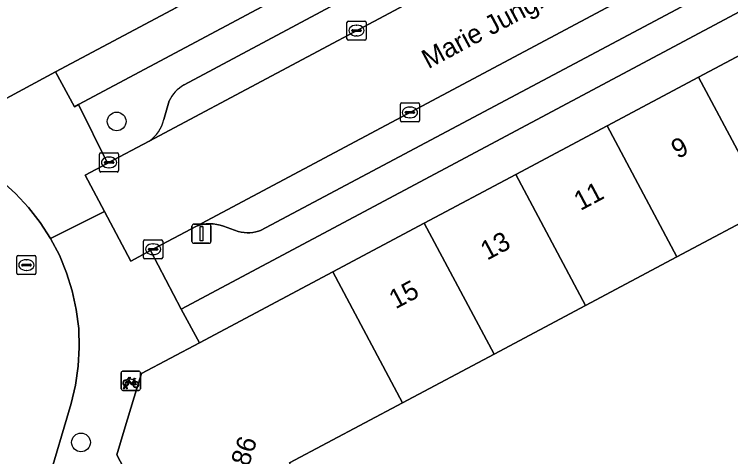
# Model space of a CAD drawing. Extents: x 160304 to 160955, y 383684 to 384161.
# Drawn here: x 160599.67 to 160637.11, y 383862.76 to 383885.89 of the extents above; entities that cross this region are included whole.
import ezdxf

# ---------------------------------------------------------------- set-up
doc = ezdxf.new("R2010")
doc.units = 0
for name, color, linetype in [('IMGEO_Boom', 7, 'Continuous'), ('IMGEO_Erf', 7, 'Continuous'), ('IMGEO_Fietsenrek', 7, 'Continuous'), ('IMGEO_Kolk', 7, 'Continuous'), ('IMGEO_Lichtmast', 7, 'Continuous'), ('IMGEO_Openbare_ruimte_label', 7, 'Continuous'), ('IMGEO_Pand', 7, 'Continuous'), ('IMGEO_Pand_nummerreeks', 7, 'Continuous'), ('IMGEO_Parkeervlak_open', 7, 'Continuous'), ('IMGEO_Rijbaan_lokaal_open', 7, 'Continuous'), ('IMGEO_Voetpad_open', 7, 'Continuous')]:
    doc.layers.add(name, color=color, linetype=linetype)

msp = doc.modelspace()

# ---------------------------------------------------------------- linework, layer by layer
at = {"layer": 'IMGEO_Boom'}
for centre in [(160605.02, 383880.291), (160603.156, 383863.502)]:
    msp.add_circle(centre, 0.489, dxfattribs=at)
at = {"layer": 'IMGEO_Erf'}
for points in [[(160599.049, 383890.783), (160599.714, 383890.581), (160604.477, 383893.118), (160609.434, 383895.758), (160614.39, 383898.398), (160619.346, 383901.038), (160624.41, 383903.736), (160628.072, 383896.861), (160623.008, 383894.164), (160618.052, 383891.524), (160613.096, 383888.884), (160608.139, 383886.243), (160601.831, 383882.883), (160602.81, 383881.06), (160603.019, 383881.171), (160630.716, 383895.952), (160629.871, 383897.643), (160619.737, 383916.693)], [(160639.077, 383875.76), (160634.299, 383873.215), (160629.519, 383870.669), (160624.74, 383868.124), (160619.961, 383865.579), (160614.056, 383862.434)]]:
    msp.add_lwpolyline(points, dxfattribs=at)
msp.add_lwpolyline([(160660.662, 383898.369), (160608.385, 383870.479), (160609.342, 383868.714), (160616.314, 383872.427), (160621.093, 383874.972), (160625.873, 383877.517), (160630.652, 383880.062), (160635.431, 383882.608), (160640.21, 383885.153), (160644.989, 383887.698), (160649.769, 383890.243), (160654.548, 383892.788), (160661.53, 383896.507)], close=True, dxfattribs=at)
at = {"layer": 'IMGEO_Fietsenrek'}
for p, q in [((160605.258, 383866.301), (160605.258, 383867.142)), ((160605.258, 383867.142), (160605.258, 383866.301)), ((160605.333, 383867.226), (160606.174, 383867.226)), ((160606.174, 383867.226), (160605.333, 383867.226)), ((160606.258, 383867.151), (160606.258, 383866.31)), ((160606.258, 383866.31), (160606.258, 383867.151)), ((160605.945, 383866.775), (160605.981, 383866.68)), ((160606.183, 383866.226), (160605.342, 383866.226)), ((160605.342, 383866.226), (160606.183, 383866.226)), ((160605.385, 383866.31), (160605.424, 383866.47)), ((160605.419, 383866.31), (160605.385, 383866.31)), ((160605.454, 383866.458), (160605.419, 383866.31)), ((160605.496, 383866.482), (160605.495, 383866.486)), ((160605.537, 383866.31), (160605.503, 383866.452)), ((160605.527, 383866.493), (160605.528, 383866.486)), ((160605.535, 383866.456), (160605.57, 383866.31)), ((160605.57, 383866.31), (160605.537, 383866.31))]:
    msp.add_line(p, q, dxfattribs=at)
for points in [[(160605.571, 383866.752), (160605.666, 383866.916), (160605.752, 383866.902), (160605.754, 383866.893), (160605.698, 383866.882), (160605.671, 383866.837), (160605.927, 383866.796)], [(160605.592, 383866.7), (160605.54, 383866.61), (160605.5, 383866.585), (160605.501, 383866.632), (160605.556, 383866.726)], [(160605.867, 383866.508), (160605.817, 383866.508), (160605.626, 383866.759), (160605.607, 383866.727)], [(160605.914, 383866.771), (160605.657, 383866.812), (160605.64, 383866.783), (160605.807, 383866.563), (160605.914, 383866.771)], [(160605.962, 383866.673), (160605.932, 383866.75), (160605.823, 383866.532), (160605.866, 383866.532)], [(160605.896, 383866.532), (160606.016, 383866.531), (160605.972, 383866.645)], [(160605.992, 383866.652), (160606.047, 383866.507), (160605.897, 383866.507)], [(160605.927, 383866.796), (160605.952, 383866.845), (160605.946, 383866.849), (160605.923, 383866.853), (160605.911, 383866.86), (160605.91, 383866.863), (160605.912, 383866.868), (160606.007, 383866.853), (160606.009, 383866.843), (160605.999, 383866.83), (160605.987, 383866.824), (160605.973, 383866.83), (160605.945, 383866.775)]]:
    msp.add_lwpolyline(points, dxfattribs=at)
for centre, radius, start, end in [((160605.336, 383867.148), 0.0779, 92.4484, 184.2845), ((160605.336, 383867.148), 0.0779, 92.4484, 184.2845), ((160606.18, 383867.148), 0.0779, 2.4484, 94.2845), ((160606.18, 383867.148), 0.0779, 2.4484, 94.2845), ((160605.498, 383866.611), 0.159, 62.6766, 242.1369), ((160605.498, 383866.611), 0.129, 63.3192, 238.903), ((160605.478, 383866.482), 0.0499, 12.8025, 158.6934), ((160605.498, 383866.611), 0.129, 283.6043, 43.4302), ((160605.498, 383866.611), 0.159, 283.5766, 46.6042), ((160606.025, 383866.527), 0.159, 113.3408, 178.3217), ((160606.025, 383866.527), 0.159, 187.0065, 105.7708), ((160606.025, 383866.527), 0.129, 113.923, 177.9556), ((160606.025, 383866.527), 0.129, 188.6715, 104.5883), ((160605.336, 383866.304), 0.0779, 182.4484, 274.2845), ((160605.336, 383866.304), 0.0779, 182.4484, 274.2845), ((160605.498, 383866.611), 0.159, 253.9967, 271.7867), ((160605.478, 383866.482), 0.0174, 12.8025, 163.4502), ((160605.498, 383866.611), 0.129, 253.415, 269.0204), ((160606.18, 383866.304), 0.0779, 272.4484, 4.2845), ((160606.18, 383866.304), 0.0779, 272.4484, 4.2845)]:
    msp.add_arc(centre, radius, start, end, dxfattribs=at)
at = {"layer": 'IMGEO_Kolk'}
for p, q in [((160617.053, 383884.617), (160617.053, 383885.469)), ((160617.128, 383885.543), (160617.98, 383885.543)), ((160617.541, 383885.323), (160617.566, 383885.323)), ((160618.054, 383885.469), (160618.054, 383884.617)), ((160617.312, 383885.037), (160617.312, 383885.049)), ((160617.75, 383885), (160617.352, 383885)), ((160617.355, 383885.086), (160617.753, 383885.086)), ((160617.796, 383885.049), (160617.796, 383885.037)), ((160617.98, 383884.543), (160617.128, 383884.543)), ((160617.564, 383884.763), (160617.539, 383884.763)), ((160619.844, 383880.336), (160619.844, 383881.188)), ((160619.919, 383881.262), (160620.771, 383881.262)), ((160620.845, 383881.188), (160620.845, 383880.336)), ((160620.103, 383880.756), (160620.103, 383880.768)), ((160620.146, 383880.805), (160620.544, 383880.805)), ((160620.332, 383881.042), (160620.357, 383881.042)), ((160620.587, 383880.768), (160620.587, 383880.756)), ((160620.541, 383880.719), (160620.143, 383880.719)), ((160620.355, 383880.482), (160620.33, 383880.482)), ((160620.771, 383880.262), (160619.919, 383880.262)), ((160604.122, 383877.72), (160604.122, 383878.572)), ((160604.197, 383878.646), (160605.049, 383878.646)), ((160605.123, 383878.572), (160605.123, 383877.72)), ((160604.381, 383878.14), (160604.381, 383878.152)), ((160604.424, 383878.189), (160604.822, 383878.189)), ((160604.61, 383878.426), (160604.635, 383878.426)), ((160604.865, 383878.152), (160604.865, 383878.14)), ((160604.819, 383878.103), (160604.421, 383878.103)), ((160604.633, 383877.866), (160604.608, 383877.866)), ((160605.049, 383877.646), (160604.197, 383877.646)), ((160606.424, 383873.178), (160606.424, 383874.03)), ((160606.499, 383874.104), (160607.351, 383874.104)), ((160607.425, 383874.03), (160607.425, 383873.178)), ((160606.726, 383873.647), (160607.124, 383873.647)), ((160606.912, 383873.884), (160606.937, 383873.884)), ((160599.878, 383873.28), (160600.73, 383873.28)), ((160606.683, 383873.598), (160606.683, 383873.61)), ((160607.121, 383873.561), (160606.723, 383873.561)), ((160606.935, 383873.324), (160606.91, 383873.324)), ((160607.167, 383873.61), (160607.167, 383873.598)), ((160599.803, 383872.354), (160599.803, 383873.206)), ((160600.291, 383873.06), (160600.316, 383873.06)), ((160600.804, 383873.206), (160600.804, 383872.354)), ((160607.351, 383873.104), (160606.499, 383873.104)), ((160600.062, 383872.774), (160600.062, 383872.786)), ((160600.5, 383872.737), (160600.102, 383872.737)), ((160600.105, 383872.823), (160600.503, 383872.823)), ((160600.546, 383872.786), (160600.546, 383872.774)), ((160600.73, 383872.28), (160599.878, 383872.28)), ((160600.314, 383872.5), (160600.289, 383872.5))]:
    msp.add_line(p, q, dxfattribs=at)
for points in [[(160617.053, 383884.617), (160617.053, 383885.469)], [(160617.128, 383885.543), (160617.98, 383885.543)], [(160618.054, 383885.469), (160618.054, 383884.617)], [(160617.98, 383884.543), (160617.128, 383884.543)], [(160619.844, 383880.336), (160619.844, 383881.188)], [(160619.919, 383881.262), (160620.771, 383881.262)], [(160620.845, 383881.188), (160620.845, 383880.336)], [(160620.771, 383880.262), (160619.919, 383880.262)], [(160604.122, 383877.72), (160604.122, 383878.572)], [(160604.197, 383878.646), (160605.049, 383878.646)], [(160605.123, 383878.572), (160605.123, 383877.72)], [(160605.049, 383877.646), (160604.197, 383877.646)], [(160606.424, 383873.178), (160606.424, 383874.03)], [(160606.499, 383874.104), (160607.351, 383874.104)], [(160607.425, 383874.03), (160607.425, 383873.178)], [(160599.878, 383873.28), (160600.73, 383873.28)], [(160599.803, 383872.354), (160599.803, 383873.206)], [(160600.804, 383873.206), (160600.804, 383872.354)], [(160607.351, 383873.104), (160606.499, 383873.104)], [(160600.73, 383872.28), (160599.878, 383872.28)]]:
    msp.add_lwpolyline(points, dxfattribs=at)
for centre, radius, start, end in [((160617.13, 383885.467), 0.0765, 91.552, 178.448), ((160617.13, 383885.467), 0.0765, 91.552, 178.448), ((160617.978, 383885.467), 0.0765, 1.552, 88.448), ((160617.978, 383885.467), 0.0765, 1.552, 88.448), ((160617.352, 383885.046), 0.0403, 85.8775, 175.7526), ((160617.349, 383885.036), 0.0366, 178.938, 274.7102), ((160617.753, 383885.043), 0.043, 264.8664, 352.4533), ((160617.757, 383885.048), 0.0386, 1.7309, 96.639), ((160617.13, 383884.619), 0.0765, 181.552, 268.448), ((160617.13, 383884.619), 0.0765, 181.552, 268.448), ((160617.978, 383884.619), 0.0765, 271.552, 358.448), ((160617.978, 383884.619), 0.0765, 271.552, 358.448), ((160619.921, 383881.186), 0.0765, 91.552, 178.448), ((160619.921, 383881.186), 0.0765, 91.552, 178.448), ((160620.769, 383881.186), 0.0765, 1.552, 88.448), ((160620.769, 383881.186), 0.0765, 1.552, 88.448), ((160620.143, 383880.765), 0.0403, 85.8775, 175.7526), ((160620.14, 383880.755), 0.0366, 178.938, 274.7102), ((160620.544, 383880.762), 0.043, 264.8664, 352.4533), ((160620.548, 383880.767), 0.0386, 1.7309, 96.639), ((160619.921, 383880.338), 0.0765, 181.552, 268.448), ((160619.921, 383880.338), 0.0765, 181.552, 268.448), ((160620.769, 383880.338), 0.0765, 271.552, 358.448), ((160620.769, 383880.338), 0.0765, 271.552, 358.448), ((160604.199, 383878.57), 0.0765, 91.552, 178.448), ((160604.199, 383878.57), 0.0765, 91.552, 178.448), ((160605.047, 383878.57), 0.0765, 1.552, 88.448), ((160605.047, 383878.57), 0.0765, 1.552, 88.448), ((160604.421, 383878.149), 0.0403, 85.8775, 175.7526), ((160604.418, 383878.139), 0.0366, 178.938, 274.7102), ((160604.822, 383878.146), 0.043, 264.8664, 352.4533), ((160604.826, 383878.151), 0.0386, 1.7309, 96.639), ((160604.199, 383877.722), 0.0765, 181.552, 268.448), ((160604.199, 383877.722), 0.0765, 181.552, 268.448), ((160605.047, 383877.722), 0.0765, 271.552, 358.448), ((160605.047, 383877.722), 0.0765, 271.552, 358.448), ((160606.501, 383874.028), 0.0765, 91.552, 178.448), ((160606.501, 383874.028), 0.0765, 91.552, 178.448), ((160607.349, 383874.028), 0.0765, 1.552, 88.448), ((160607.349, 383874.028), 0.0765, 1.552, 88.448), ((160606.723, 383873.607), 0.0403, 85.8775, 175.7526), ((160607.128, 383873.609), 0.0386, 1.7309, 96.639), ((160599.88, 383873.204), 0.0765, 91.552, 178.448), ((160599.88, 383873.204), 0.0765, 91.552, 178.448), ((160600.728, 383873.204), 0.0765, 1.552, 88.448), ((160600.728, 383873.204), 0.0765, 1.552, 88.448), ((160606.72, 383873.597), 0.0366, 178.938, 274.7102), ((160607.124, 383873.604), 0.043, 264.8664, 352.4533), ((160606.501, 383873.18), 0.0765, 181.552, 268.448), ((160606.501, 383873.18), 0.0765, 181.552, 268.448), ((160607.349, 383873.18), 0.0765, 271.552, 358.448), ((160607.349, 383873.18), 0.0765, 271.552, 358.448), ((160600.102, 383872.783), 0.0403, 85.8775, 175.7526), ((160600.099, 383872.773), 0.0366, 178.938, 274.7102), ((160600.503, 383872.78), 0.043, 264.8664, 352.4533), ((160600.507, 383872.785), 0.0386, 1.7309, 96.639), ((160599.88, 383872.356), 0.0765, 181.552, 268.448), ((160599.88, 383872.356), 0.0765, 181.552, 268.448), ((160600.728, 383872.356), 0.0765, 271.552, 358.448), ((160600.728, 383872.356), 0.0765, 271.552, 358.448)]:
    msp.add_arc(centre, radius, start, end, dxfattribs=at)
for centre, major_axis, ratio, start_param, end_param in [((160617.54, 383885.043), (-0.387, 0.002), 0.722429, 4.712389, 7.853982), ((160617.565, 383885.043), (-0.39, 0.002), 0.717154, 1.570796, 4.712389), ((160620.331, 383880.762), (-0.387, 0.002), 0.722429, 4.712389, 7.853982), ((160620.356, 383880.762), (-0.39, 0.002), 0.717154, 1.570796, 4.712389), ((160604.609, 383878.146), (-0.387, 0.002), 0.722429, 4.712389, 7.853982), ((160604.634, 383878.146), (-0.39, 0.002), 0.717154, 1.570796, 4.712389), ((160606.911, 383873.604), (-0.387, 0.002), 0.722429, 4.712389, 7.853982), ((160606.936, 383873.604), (-0.39, 0.002), 0.717154, 1.570796, 4.712389), ((160600.29, 383872.78), (-0.387, 0.002), 0.722429, 4.712389, 7.853982), ((160600.315, 383872.78), (-0.39, 0.002), 0.717154, 1.570796, 4.712389)]:
    msp.add_ellipse(centre, major_axis=major_axis, ratio=ratio, start_param=start_param, end_param=end_param, dxfattribs=at)
at = {"layer": 'IMGEO_Lichtmast'}
for p, q in [((160608.956, 383874.017), (160608.956, 383874.817)), ((160608.956, 383874.817), (160608.956, 383874.017)), ((160609.056, 383874.917), (160609.846, 383874.917)), ((160609.846, 383874.917), (160609.056, 383874.917)), ((160609.946, 383874.817), (160609.946, 383874.017)), ((160609.946, 383874.017), (160609.946, 383874.817)), ((160609.846, 383873.917), (160609.056, 383873.917)), ((160609.056, 383873.917), (160609.846, 383873.917))]:
    msp.add_line(p, q, dxfattribs=at)
msp.add_lwpolyline([(160609.376, 383874.792), (160609.526, 383874.792), (160609.526, 383874.042), (160609.376, 383874.042), (160609.376, 383874.792)], dxfattribs=at)
for centre, start, end in [((160609.056, 383874.817), 90, 180), ((160609.056, 383874.817), 90, 180), ((160609.846, 383874.817), 0, 90), ((160609.846, 383874.817), 360, 90), ((160609.056, 383874.017), 180, 270), ((160609.056, 383874.017), 180, 270), ((160609.846, 383874.017), 270, 0), ((160609.846, 383874.017), 270, 0)]:
    msp.add_arc(centre, 0.1, start, end, dxfattribs=at)
at = {"layer": 'IMGEO_Pand'}
for points in [[(160604.477, 383893.118), (160599.714, 383890.581), (160599.049, 383890.783), (160597.603, 383893.497), (160590.792, 383889.87), (160593.071, 383885.591), (160594.706, 383882.522), (160595.841, 383882.177), (160597.563, 383881.652), (160598.806, 383881.272), (160601.831, 383882.883), (160608.139, 383886.243)], [(160635.431, 383882.608), (160639.077, 383875.76), (160643.857, 383878.306), (160640.21, 383885.153)], [(160630.652, 383880.062), (160634.299, 383873.215), (160639.077, 383875.76), (160635.431, 383882.608)], [(160630.652, 383880.062), (160625.873, 383877.517), (160629.519, 383870.669), (160634.299, 383873.215)], [(160624.74, 383868.124), (160629.519, 383870.669), (160625.873, 383877.517), (160621.093, 383874.972)], [(160624.74, 383868.124), (160621.093, 383874.972), (160616.314, 383872.427), (160619.961, 383865.579)], [(160614.056, 383862.434), (160619.961, 383865.579), (160616.314, 383872.427), (160609.342, 383868.714), (160606.323, 383867.106), (160605.944, 383865.863), (160605.42, 383864.141), (160605.024, 383862.845), (160606.586, 383859.913), (160610.063, 383853.384), (160616.932, 383857.033)]]:
    msp.add_lwpolyline(points, close=True, dxfattribs=at)
at = {"layer": 'IMGEO_Parkeervlak_open'}
for points in [[(160660.608, 383902.238), (160609.197, 383874.818), (160609.343, 383874.864), (160609.522, 383874.905), (160609.703, 383874.93), (160609.886, 383874.938), (160610.069, 383874.93), (160610.25, 383874.906), (160610.429, 383874.865), (160610.603, 383874.809), (160611.378, 383874.542), (160611.527, 383874.503), (160611.678, 383874.478), (160611.832, 383874.466), (160611.985, 383874.468), (160612.138, 383874.484), (160612.289, 383874.513), (160612.437, 383874.556), (160612.533, 383874.592), (160659.026, 383899.322)], [(160606.718, 383879.264), (160633.401, 383893.494)], [(160630.237, 383893.81), (160608.541, 383882.199)], [(160607.766, 383881.362), (160607.485, 383880.384)]]:
    msp.add_lwpolyline(points, dxfattribs=at)
for centre, radius, start, end in [((160609.417, 383880.61), 1.814, 118.8779, 155.5273), ((160605.709, 383880.778), 1.82, 303.6933, 347.4983)]:
    msp.add_arc(centre, radius, start, end, dxfattribs=at)
at = {"layer": 'IMGEO_Rijbaan_lokaal_open'}
for points in [[(160666.813, 383911.312), (160654.821, 383904.917), (160637.105, 383895.469), (160636.895, 383895.357), (160633.542, 383893.569), (160633.401, 383893.494), (160606.718, 383879.264), (160604.537, 383878.101), (160604.496, 383878.079), (160603.369, 383877.478), (160604.38, 383875.585), (160605.766, 383872.988), (160606.789, 383873.534), (160609.197, 383874.818), (160660.608, 383902.238), (160661.913, 383902.934), (160669.77, 383907.125)], [(160601.409, 383861.36), (160602.642, 383865.533), (160602.872, 383866.499), (160603.015, 383867.482), (160603.07, 383868.474), (160603.036, 383869.467), (160602.913, 383870.453), (160602.702, 383871.424), (160602.406, 383872.372), (160602.026, 383873.29), (160601.566, 383874.171), (160601.029, 383875.006), (160600.42, 383875.791), (160599.742, 383876.518), (160599.003, 383877.181), (160598.207, 383877.776), (160597.361, 383878.297), (160596.473, 383878.741), (160595.731, 383879.039), (160590.253, 383880.91)]]:
    msp.add_lwpolyline(points, dxfattribs=at)
at = {"layer": 'IMGEO_Voetpad_open'}
for points in [[(160657.72, 383910.303), (160653.56, 383908.079), (160643.629, 383902.793), (160635.231, 383898.324), (160634.341, 383899.993), (160631.296, 383898.376), (160629.871, 383897.643), (160630.716, 383895.952), (160603.019, 383881.171), (160604.537, 383878.101), (160606.718, 383879.264)], [(160659.026, 383899.322), (160612.533, 383874.592), (160612.437, 383874.556), (160612.289, 383874.513), (160612.138, 383874.484), (160611.985, 383874.468), (160611.832, 383874.466), (160611.678, 383874.478), (160611.527, 383874.503), (160611.378, 383874.542), (160610.603, 383874.809), (160610.429, 383874.865), (160610.25, 383874.906), (160610.069, 383874.93), (160609.886, 383874.938), (160609.703, 383874.93), (160609.522, 383874.905), (160609.343, 383874.864), (160609.197, 383874.818), (160606.789, 383873.534), (160608.385, 383870.479), (160660.662, 383898.369)], [(160608.541, 383882.199), (160630.237, 383893.81)], [(160599.003, 383877.181), (160599.742, 383876.518), (160600.42, 383875.791), (160601.029, 383875.006), (160601.566, 383874.171), (160604.38, 383875.585), (160603.369, 383877.478), (160604.496, 383878.079), (160604.537, 383878.101), (160603.019, 383881.171), (160602.81, 383881.06), (160601.831, 383882.883), (160598.806, 383881.272)], [(160607.485, 383880.384), (160607.766, 383881.362)], [(160606.586, 383859.913), (160605.024, 383862.845), (160605.42, 383864.141), (160605.944, 383865.863), (160606.323, 383867.106), (160609.342, 383868.714), (160608.385, 383870.479), (160606.789, 383873.534), (160605.766, 383872.988), (160604.38, 383875.585), (160601.566, 383874.171), (160602.026, 383873.29), (160602.406, 383872.372), (160602.702, 383871.424), (160602.913, 383870.453), (160603.036, 383869.467), (160603.07, 383868.474), (160603.015, 383867.482), (160602.872, 383866.499), (160602.642, 383865.533), (160601.409, 383861.36)]]:
    msp.add_lwpolyline(points, dxfattribs=at)
for centre, radius, start, end in [((160609.417, 383880.61), 1.814, 118.8779, 155.5273), ((160605.709, 383880.778), 1.82, 303.6933, 347.4983)]:
    msp.add_arc(centre, radius, start, end, dxfattribs=at)

# ---------------------------------------------------------------- texts
at = {"layer": 'IMGEO_Openbare_ruimte_label'}
msp.add_text('Marie Jungiusstraat', height=1, rotation=28.1028, dxfattribs=at).set_placement((160621.307, 383883.022))
at = {"layer": 'IMGEO_Pand_nummerreeks'}
for s, rotation, p in [('9', 28.0369, (160634.34, 383878.31)), ('11', 28.0369, (160629.255, 383875.602)), ('13', 28.0369, (160624.376, 383873.004)), ('15', 28.0369, (160619.597, 383870.459)), ('76-86', 72.2156, (160611.328, 383860.355))]:
    msp.add_text(s, height=1, rotation=rotation, dxfattribs=at).set_placement(p)

doc.saveas('drawing.dxf')
